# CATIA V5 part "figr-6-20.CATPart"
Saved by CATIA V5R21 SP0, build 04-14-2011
Part number: Part1
Bounding box of the stored display mesh (mm): x 0 to 150, y -70 to 70, z -150 to 69.804
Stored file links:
  D:\CATIA V5R21 E-RESOURCES\CATIA-V5R21\catia-v5r21-prt\c06-catia-v5r21-prt\c06-catia-v5r21-figr-6-20.CATPart
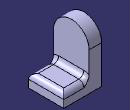
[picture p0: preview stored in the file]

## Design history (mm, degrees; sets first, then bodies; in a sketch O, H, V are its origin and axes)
Body1 (main body)
  Sketch1 on yz-plane, origin (0, 0, 0), H (0, 1, 0), V (0, 0, 1)
    arc A1 centre (0, 0) radius 70 from (70, 0) to (-70, 0) ccw
    point P1 (70, 0)
    point P2 (-70, 0)
    line L1 (-70, 0) -> (-70, -150)
    line L2 (-70, -150) -> (70, -150)
    line L3 (70, -150) -> (70, 0)
    construction circle A2 centre (0, 0) radius 37.5
    radius A1 = 70
    radius A2 = 37.5
    distance O L2 = 150
    coincidence: P1 H, P2 H
    tangency: L1 A1, L3 A1
    horizontal: L2 H
  Pad1: profile Sketch1, direction (1, 0, 0), length 50
  Sketch2 on face of Pad1, origin (50, 0, 0), H (0, 1, 0), V (0, 0, 1)
    line L1 (-70, -150) -> (70, -150)
    line L2 (70, -150) -> (70, -100)
    line L3 (70, -100) -> (-70, -100)
    line L4 (-70, -100) -> (-70, -150)
    reference projected line E1 (-70, -150) -> (70, -150) from edge [face of Pad1 | face of Pad1]
    reference projected line E2 (-70, 0) -> (-70, -150) from edge [face of Pad1 | face of Pad1]
    reference projected line E3 (70, -150) -> (70, 0) from edge [face of Pad1 | face of Pad1]
    length L2 = 50
    horizontal: L1 H, L3 H
    vertical: L2 V, L4 V
    coincidence: L1 E1, E2 L4, L2 E3
  Pad2: profile Sketch2, direction (1, 0, 0), length 100
  Fillet1: radius 20, on face of Pad2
